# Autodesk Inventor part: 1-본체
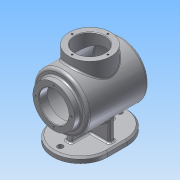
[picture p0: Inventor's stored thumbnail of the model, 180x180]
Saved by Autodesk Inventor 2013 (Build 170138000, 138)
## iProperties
Created: 2016-04
Part Number: 1-본체
Material: 알루미늄 6061
Document SubType Name: Modeling
Designer: Administrator
Density: 2.71 g/cm^3
Mass: 936.549 g
Surface Area: 1291.45 cm^2
Volume: 345.59 cm^3
Author: Administrator
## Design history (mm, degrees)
sketch "스케치1"
  geometry: L1 (-17.5, 50)-(17.5, 50); L2 (17.5, -50)-(-17.5, -50); A1 r 50 centre (17.5, 0) between (17.5, -50) and (17.5, 50); A2 r 50 centre (-17.5, 0) between (-17.5, 50) and (-17.5, -50); 2 further points
  constraints: 4 end point, 4 point on circle, 2 centre point, 2 horizontal alignment, 2 tangent, 1 equal radius, 1 horizontal, 1 midpoint, 1 parallel, 1 vertical alignment
  dimensions: "d86" = 100 distance of L2.start L1.end; "d88" = 135 dimension on A1 A2
extrude "돌출1" new body sketch "스케치1" distance "d3" = 10; taper "d4" = 0 deg
node "작업 평면2"
sketch "스케치10"
  geometry: L1 (-65.924, 79)-(65.924, 79); L2 (-65.924, 79)-(-65.924, 117); L3 (-65.924, 117)-(-53.924, 117); L4 (-53.924, 117)-(-53.924, 129); L5 (-53.924, 129)-(56.076, 129); L6 (17.5, 0)-(-17.5, 0) reference; A1 r 131.848 centre (-65.924, 79) between (65.924, 79) and (56.076, 129); 3 further points
  constraints: 10 end point, 2 midpoint, 2 parallel, 2 point on circle, 2 vertical alignment, 1 centre point, 1 coincident, 1 horizontal, 1 perpendicular
  dimensions: "d48" = 76 diameter of L3 L1; "d49" = 12 distance of L2.end L3.end; "d50" = 100 diameter of L5 L1; "d53" = 110 horizontal distance of L5.end L3.end; "d90" = 158 diameter of L6 L1
revolve "회전2" sketch "스케치10" stored, may be unused: angle "d55" = 90 deg
sketch "스케치11"
  geometry: L1 (-53.924, 29)-(-53.924, 129) reference; L2 (55.544, 29)-(55.544, 129) reference; L3 (-53.924, 129)-(56.076, 129) reference; L4 (-53.924, 29)-(56.076, 29) reference; L5 (-50.924, 126)-(53.601, 126); L6 (-50.924, 79)-(-50.924, 126); L7 (-50.924, 79)-(63.456, 79); A1 r 117 centre (-53.544, 79) between (63.456, 79) and (53.601, 126); 6 further points; 1 other entity
  constraints: 6 end point, 2 horizontal alignment, 2 parallel, 2 point on circle, 1 centre point, 3 other
  dimensions: "d56" = 3 distance between parallel lines of L3 L5; "d57" = 3 dimension on A1; "d58" = 3 distance between parallel lines of L1 L6
revolve "회전3" sketch "스케치11" stored, may be unused: angle "d60" = 90 deg
hole "구멍2" diameter "d63" = 54; stored, may be unused: countersink angle "d67" = 90 deg, drill point angle "d69" = 0 deg; dims "d61" = 10, "d62" = 10, "d64" = 6, "d65" = 54, "d66" = 15, "d68" = 15
node "작업 평면3"
sketch "스케치12"
  geometry: C1 r 38 at (0, 0); 1 further point
  constraints: 1 centre point, 1 coincident
  dimensions: "d71" = 76 diameter of C1
extrude "돌출6" join sketch "스케치12" stored distance "d73" = 15; taper "d74" = 0 deg
hole "구멍3" diameter "d77" = 54; stored, may be unused: countersink angle "d81" = 90 deg, drill point angle "d83" = 0 deg; dims "d75" = 10, "d76" = 10, "d78" = 6, "d79" = 54, "d80" = 15, "d82" = 30
sketch "스케치14"
  geometry: 3 further points
  constraints: 2 horizontal alignment
  dimensions: "d91" = 54 distance of point (0, 0) point (-54, 0); "d92" = 54 distance of point (54, 0) point (0, 0)
hole "구멍4" sketch "스케치14" at (-54, 0), (54, 0) diameter "d93" = 10; stored, may be unused: countersink angle "d97" = 90 deg, drill point angle "d99" = 0 deg; dims "d94" = 6, "d95" = 54, "d96" = 15, "d98" = 30
sketch "스케치16"
  geometry: L1 (50, 10)-(-50, 10) reference; L2 (-40, 10)-(-40, 49); L3 (40, 49)-(40, 10); A1 r 50 centre (0, 79) between (-40, 49) and (40, 49) reference; 1 further point
  constraints: 4 end point, 2 point on circle, 2 point on line
  dimensions: "d105" = 90 deg angle of L1 L2; "d106" = 40 horizontal distance of point (0, 0) L2.start; "d107" = 40 horizontal distance of point (0, 0) L3.end; "d108" = 90 deg angle of L1 L3
extrude "돌출8" join sketch "스케치16" stored distance "d109" = 10; taper "d110" = 0 deg
sketch "스케치17"
  geometry: L1 (-53.924, 29)-(56.076, 29) reference; L2 (-17.5, 10)-(-67.5, 10) reference; L3 (67.5, 10)-(17.5, 10) reference; L4 (-36.65, 29)-(-40, 10); L5 (36.65, 29)-(40, 10); 1 further point
  constraints: 4 end point, 4 point on line
  dimensions: "d111" = 40 horizontal distance of L4.end point (0, 0); "d112" = 40 horizontal distance of L5.end point (0, 0); "d113" = 100 deg angle of L2 L4; "d114" = 100 deg angle of L3 L5
feature "리브1" dims "d115" = 1, "d116" = 10, "d117" = 0, "d118" = 0, "d119" = 1, "d120" = 1
feature "리브2" dims "d121" = 1, "d122" = 10, "d123" = 0, "d124" = 0, "d125" = 1, "d126" = 1
sketch "스케치18" dims "d127" = 65
  geometry: C1 r 50 at (0, 0) reference; C2 r 38 at (0, 0) reference; 3 further points
  constraints: 2 vertical alignment, 1 coincident, 2 other
hole "구멍5" sketch "스케치18" at (0, 32.5) diameter "d129" = 3.242; stored, may be unused: countersink angle "d133" = 90 deg, drill point angle "d135" = 0 deg; dims "d130" = 8, "d131" = 54, "d132" = 15, "d134" = 10
sketch "스케치19" dims "d139" = 65
  geometry: 3 further points
  constraints: 2 vertical alignment, 1 coincident, 2 other
hole "구멍6" sketch "스케치19" at (0, 32.5) diameter "d141" = 3.242; stored, may be unused: countersink angle "d145" = 90 deg, drill point angle "d147" = 0 deg; dims "d142" = 8, "d143" = 54, "d144" = 15, "d146" = 10
fillet "모깎기1" dims "d151" = 2
fillet "모깎기2" dims "d152" = 2
fillet "모깎기3" dims "d153" = 5
fillet "모깎기4" dims "d154" = 3
fillet "모깎기5" dims "d155" = 3
chamfer "모따기1" distance "d156" = 1; stored, may be unused: second distance "d157" = 2, angle "d158" = 45 deg
fillet "모깎기6" dims "d159" = 3
fillet "모깎기7" dims "d160" = 3
chamfer "모따기2" distance "d161" = 3; stored, may be unused: second distance "d162" = 2, angle "d163" = 45 deg
node "작업 평면6"
node "작업 평면7"
node "솔리드1"
pattern_circular "원형 패턴1" dims angle "d137" = 360 deg
pattern_circular "원형 패턴2" dims angle "d149" = 360 deg
node "투영된 루프4"
node "투영된 루프5"
node "투영된 루프6"
other parameters: "d33" = 144, "d70" = 144
